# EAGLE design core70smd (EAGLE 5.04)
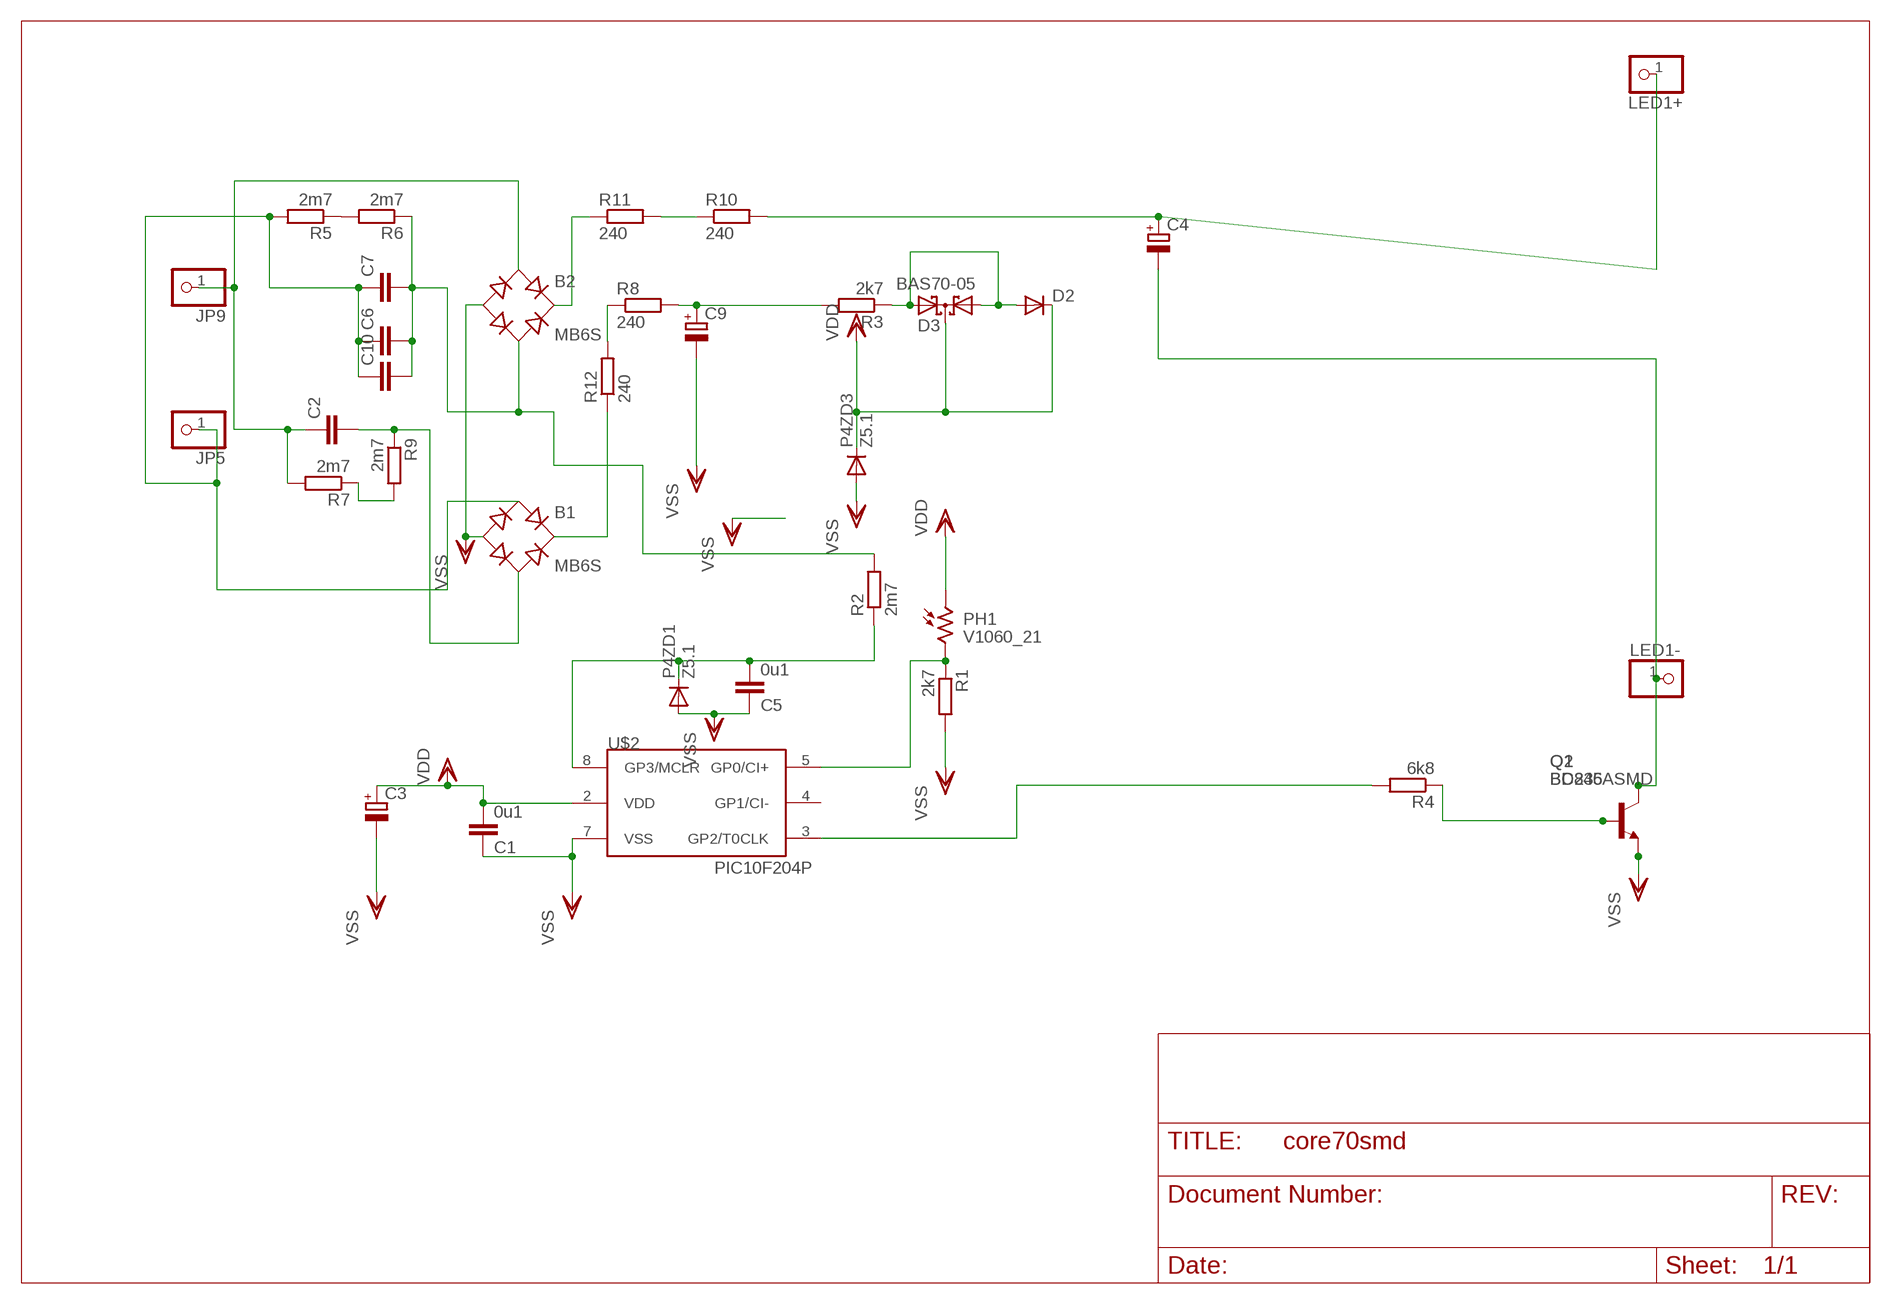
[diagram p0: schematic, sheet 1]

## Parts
B1  MB6S  [SOIC-4]
B2  MB6S  [SOIC-4]
C1  0u1  C-EUC1206  [C1206]
C2  C-EUC4564  [C4564]
C3  CPOL-EUB  [PANASONIC_B]
C4  CPOL-EUSMCE  [SMC_E]
C5  0u1  C-EUC1206  [C1206]
C6  C-EUC4564  [C4564]
C7  C-EUC4564  [C4564]
C9  CPOL-EUSMCD  [SMC_D]
C10  C-EUC4564  [C4564]
D2  DIODE-MINIMELF  [MINIMELF]
D3  BAS70-05  [SOT23]
JP5  PINHD-1X1  [1X01]
JP9  PINHD-1X1  [1X01]
LED1+  PINHD-1X1  [1X01]
LED1-  PINHD-1X1  [1X01]
P4ZD1  Z5.1  DIODE-MINIMELF  [MINIMELF]
P4ZD3  Z5.1  DIODE-MINIMELF  [MINIMELF]
PH1  V1060_21  [TO-5_V10]
Q1  BC846ASMD  [SOT23]
Q2  BD235  [TO126]
R1  2k7  R-EU_R1206  [R1206]
R2  2m7  R-EU_R1206  [R1206]
R3  2k7  R-EU_R1206  [R1206]
R4  6k8  R-EU_R1206  [R1206]
R5  2m7  R-EU_R1210  [R1210]
R6  2m7  R-EU_R1210  [R1210]
R7  2m7  R-EU_R1210  [R1210]
R8  240  R-EU_R1210  [R1210]
R9  2m7  R-EU_R1210  [R1210]
R10  240  R-EU_R2010  [R2010]
R11  240  R-EU_R2010  [R2010]
R12  240  R-EU_R1210  [R1210]
U$2  PIC10F204P  [DIL8]

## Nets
AC1: B1.~1(AC1) C6.1 C7.1 C10.1 JP5.1 R5.2
AC2: B2.~1(AC1) C2.1 JP9.1 R7.2
CBIG: B2.~2(AC2) C6.2 C7.2 C10.2 R2.2 R6.1
CSMALL: B1.~2(AC2) C2.2 R9.1
D+: C4.+ LED1+.1 R10.2
D-: C4.- LED1-.1 Q1.3(C) Q2.2(C)
DR+: C9.+ R3.2 R8.2
N$1: C5.2 P4ZD1.C R2.1 U$2.8(GP3/MCLR)
N$2: R5.1 R6.2
N$3: R7.1 R9.2
N$4: R8.1 R12.2
N$5: D2.A D3.1(A1) D3.2(A2) R3.1
N$6: R10.1 R11.2
N$11: B2.+ R11.1
N$12: Q1.1(B) Q2.3(B) R4.1
N$15: R4.2 U$2.3(GP2/T0CLK)
N$17: PH1.2 R1.1 U$2.5(GP0/CI+)
RECDR+: B1.+ R12.1
VDD: C1.2 C3.+ D2.C D3.3(C) P4ZD3.C PH1.1 U$2.2(VDD)
VSS: B1.- B2.- C1.1 C3.- C5.1 C9.- P4ZD1.A P4ZD3.A Q1.2(E) Q2.1(E) R1.2 U$2.7(VSS)
Unconnected: U$2.4(GP1/CI-)

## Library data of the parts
B1 B2 = rectifier:MB*S: Bridge Rectifier Source: http://www.fairchildsemi.com/ds/MB/MB6S.pdf
C1 C5 = rcl:C-EU: CAPACITOR, European symbol
C2 C6 C7 C10 = rcl-2:C-EU: CAPACITOR, European symbol
C3 C4 C9 = rcl-2:CPOL-EU: POLARIZED CAPACITOR, European symbol
D2 P4ZD1 P4ZD3 = diode:DIODE-: DIODE
D3 = diode:BAS70-05: Silicon Schottky Diodes General-purpose diode for high-speed switching
JP5 JP9 LED1+ LED1- = pinhead(2):PINHD-1X1: PIN HEADER
PH1 = photo-elements:?1060*: Sensor Street Light control
Q1 = transistor-npn:BC846*: NPN Transistor
Q2 = transistor-npn:BD235*: NPN Transistor
R1-R12 = rcl-2:R-EU_: RESISTOR, European symbol
U$2 = microchip-3:PIC10F2*: uPC nW 0,25/0,5k Program Flash memory Comparator

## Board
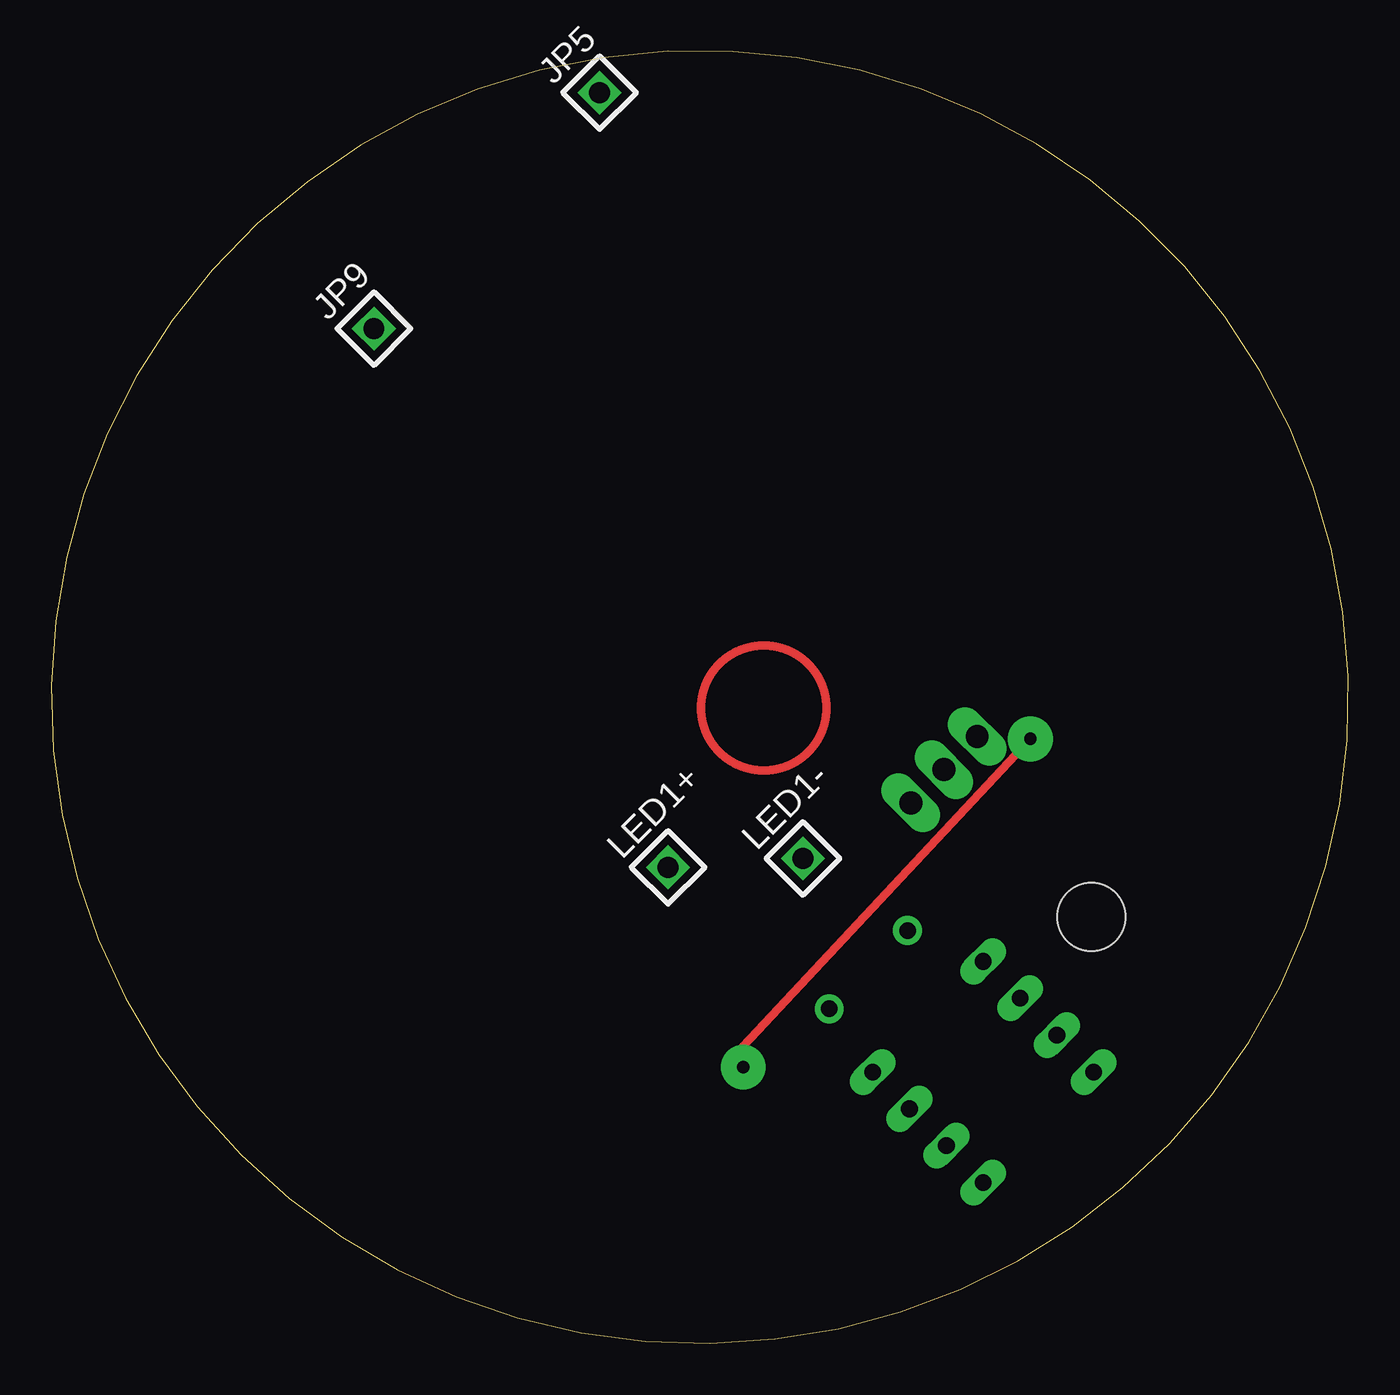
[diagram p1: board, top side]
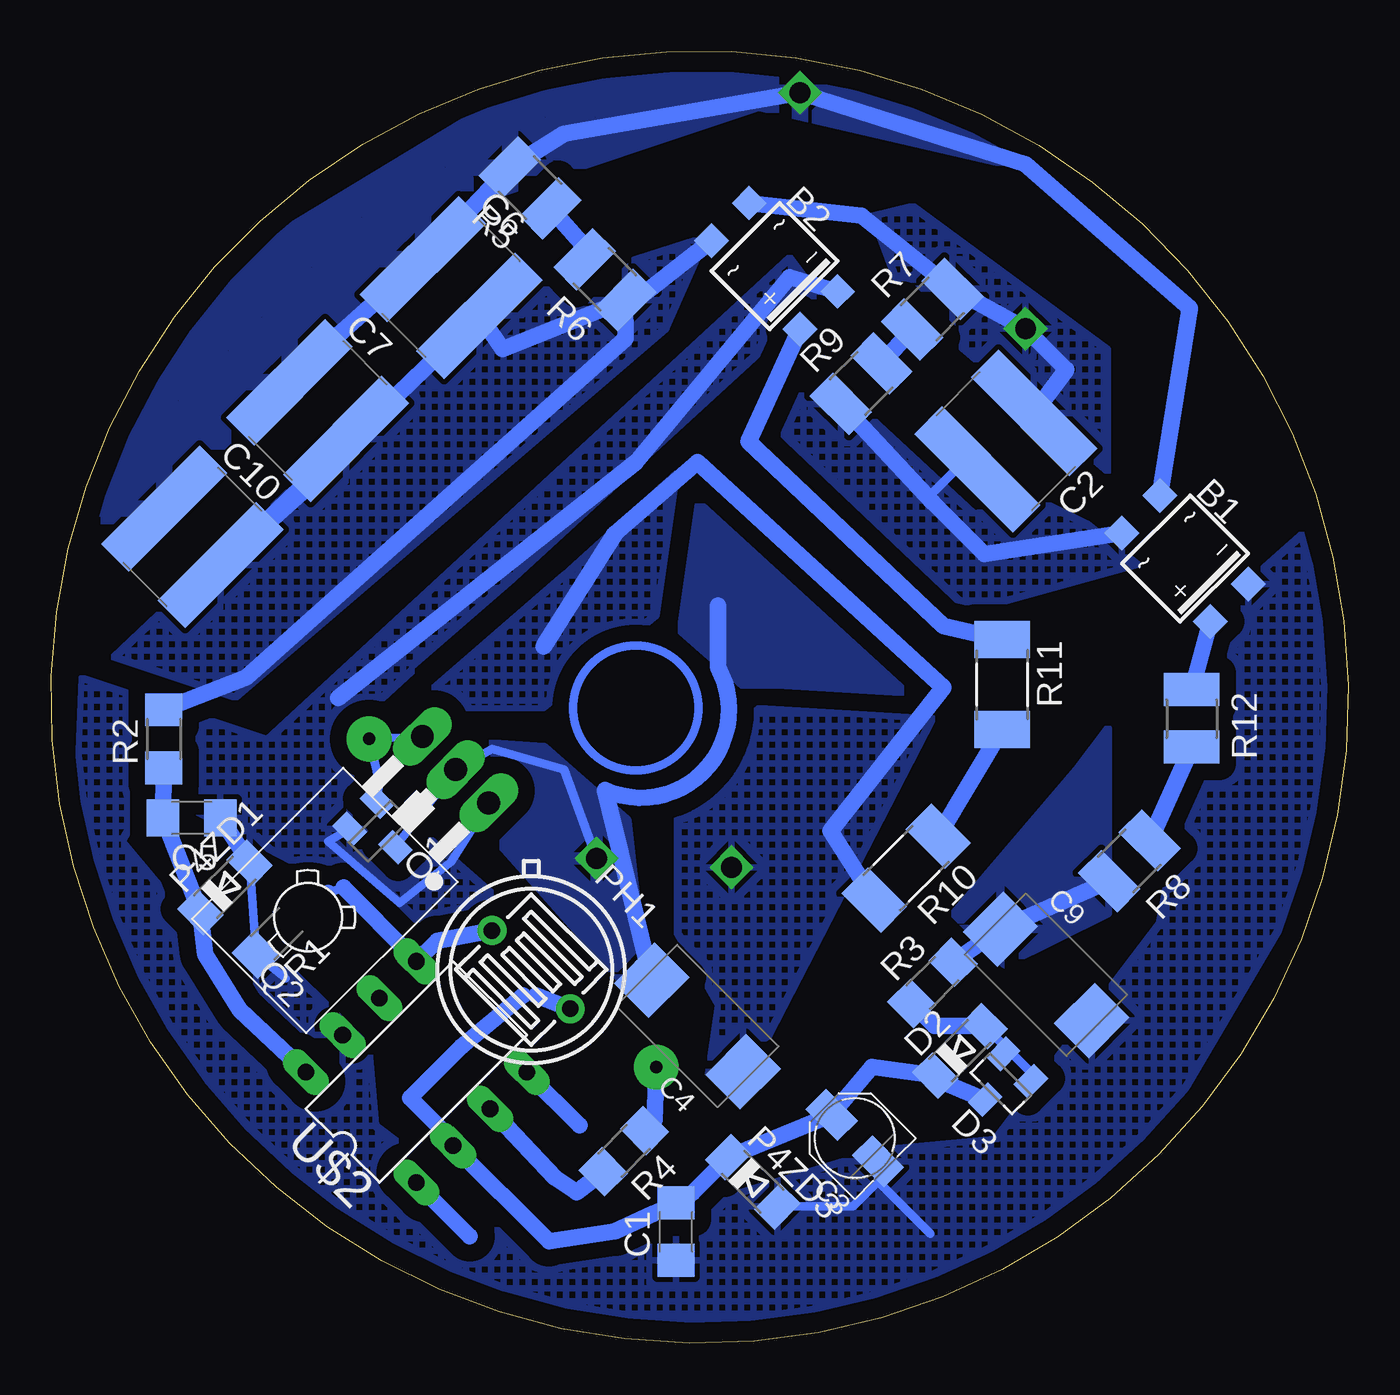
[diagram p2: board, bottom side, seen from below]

Size 63.22 x 62.98 mm. Coordinates in mm from the lower left corner, seen from the top.
Outline: 35.28,0.22 arc171 33.23,62.97 arc190 35.28,0.22
Copper layers (1*16): Top 0.035mm / dielectric 1.5mm / Bottom 0.035mm
Design rules "default": minimum track width 10mil, minimum drill 24mil, track to track 8mil, track to pad 8mil, pad to pad 8mil, via to via 8mil, smd to smd 8mil, copper to edge 40mil, drill to drill 8mil, minimum pad ring 10mil, minimum via ring 8mil, stop-mask expansion 4mil, vias tented up to drill 0mil, thermal gap 10mil

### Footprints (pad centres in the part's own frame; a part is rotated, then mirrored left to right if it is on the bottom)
SOIC-4 = smd 1.2 x 1.2: + 1.3,3.05; - -1.3,3.05; ~1 -1.3,-3.05; ~2 1.3,-3.05
C1206 = smd 1.6 x 1.8: 1 -1.4,0; 2 1.4,0
C4564 = smd 1.9 x 6.8: 1 -1.95,0; 2 1.95,0
PANASONIC_B = smd 2.2 x 1.4: + 1.6,0; - -1.6,0
SMC_E = smd 2.4 x 2.8: + -3.15,0; - 3.15,0
SMC_D = smd 2.4 x 2.8: + -3.15,0; - 3.15,0
MINIMELF = smd 1.4 x 1.8: A 1.7,0; C -1.7,0
SOT23 = smd 1 x 1.4: 1 -0.95,-1.1; 2 0.95,-1.1; 3 0,1.1
1X01 = drill 1.016 square: 1 0,0
TO-5_V10 = drill 0.8 pad 1.4 round: 1 -2.7,0; 2 2.7,0
TO126 = drill 1.118 long: 1 -2.286,-5.08; 2 0,-5.08; 3 2.286,-5.08 | hole 3.302: 0,5.08
R1206 = smd 1.6 x 1.803: 1 -1.422,0; 2 1.422,0
R1210 = smd 1.6 x 2.7: 1 -1.4,0; 2 1.4,0
R2010 = smd 1.8 x 2.7: 1 -2.2,0; 2 2.2,0
DIL8 = drill 0.813 long: 1 -3.81,-3.81; 2 -1.27,-3.81; 3 1.27,-3.81; 4 3.81,-3.81; 5 3.81,3.81; 6 1.27,3.81; 7 -1.27,3.81; 8 -3.81,3.81

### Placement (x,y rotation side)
B1  7.95,38.26 225 bottom
B2  27.96,52.52 225 bottom
C1  32.77,5.45 90 bottom
C2  16.69,43.98 225 bottom
C3  24.05,10.01 135 bottom
C4  31.73,15.47 135 bottom
C5  56.37,25.62 180 bottom
C6  43.73,51.47 315 bottom
C7  50.23,45.47 315 bottom
C9  14.73,17.97 315 bottom
C10  56.34,39.31 315 bottom
D2  18.93,14.27 45 bottom
D3  16.92,12.66 135 bottom
JP5  26.73,60.97 45 top
JP9  15.73,49.47 45 top
LED1+  30.07,23.21 45 top
LED1-  36.64,23.64 45 top
P4ZD1  54.75,22.23 45 bottom
P4ZD3  29.03,7.88 315 bottom
PH1  39.83,18.22 135 bottom
Q1  47.23,24.97 225 bottom
Q2  47.1,24.38 135 bottom
R1  52.23,19.97 225 bottom
R2  57.73,29.47 90 bottom
R3  20.27,17.57 45 bottom
R4  35.3,9.37 225 bottom
R5  39.87,56.32 135 bottom
R6  36.23,51.85 135 bottom
R7  20.27,50.41 45 bottom
R8  10.66,23.53 225 bottom
R9  23.74,46.78 45 bottom
R10  21.54,23.17 225 bottom
R11  16.87,32.12 270 bottom
R12  7.63,30.47 270 bottom
U$2  45.42,13.23 45 bottom

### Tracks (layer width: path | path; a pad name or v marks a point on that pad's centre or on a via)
AC1
  Bottom 0.813: B1.~1 7.73,50.47 15.73,57.47 JP5.1 38.23,58.97 R5.2 C6.1 52.23,46.47 C7.1
  pour Bottom (isolate 0.813, rank 4, hatched): 25.73,62.97 38.73,61.97 55.23,51.97 61.23,39.97 60.23,38.97 42.23,55.97 28.73,60.47 15.73,57.47
AC2
  Bottom 0.813: B2.~1 23.73,54.97 R7.2 JP9.1 13.73,47.47 C2.1
  pour Bottom (isolate 0.813, rank 3, hatched): 23.23,54.97 21.23,55.47 11.73,48.47 11.73,42.47 21.73,50.97
CBIG
  Bottom 0.813: B2.~2 35.23,50.47 R6.1 | R6.1 41.23,48.47 C6.2 C10.2 48.23,43.97 C7.2 | R2.2 53.73,32.47 35.23,48.97 R6.1
  pour Bottom (isolate 0.813, rank 3, hatched): 31.23,53.97 33.23,49.47 54.23,31.47 60.23,33.47 42.23,50.47
CSMALL
  Bottom 0.406: C2.2 19.11,42.6 20.48,41.24
  Bottom 0.813: B1.~2 17.73,38.47 20.23,40.97 R9.1
  pour Bottom (isolate 0.813, rank 3, hatched): 25.23,46.97 27.23,45.97 27.73,43.47 19.23,35.47 10.23,37.97 12.73,39.97 14.73,40.97 18.23,40.47
D+
  Bottom 0.813: R10.2 25.23,24.97 19.73,31.97 31.73,42.97 35.73,39.47 39.23,33.97
  pour Bottom (isolate 0.813, hatched): 38.23,37.47 45.73,30.97 39.23,30.97 33.73,35.47 32.73,42.47
  pour Bottom (isolate 0.813, hatched): 28.23,14.97 20.23,30.47 28.73,30.97 32.73,27.47 32.73,19.97 30.73,16.47 31.23,12.97
D-
  Bottom 0.406: LED1-.1 38.23,27.97 41.73,28.97 Q2.2 Q1.3
  Bottom 0.813: C4.- 36.23,26.97 arc-143 30.73,32.97 30.73,35.97
  pour Bottom (isolate 0.813, rank 2): 42.23,25.47 34.23,16.47 35.23,25.47 39.23,28.97 46.23,29.47
  pour Bottom (isolate 0.813, rank 2): 24.23,34.47 32.73,41.97 33.23,35.47 29.23,31.97 20.73,31.47
DR+
  Bottom 0.813: R8.2 C9.+ R3.2
  pour Bottom: 13.23,27.97 19.23,20.97 16.73,18.47 11.73,20.97 11.73,29.97
N$1
  Bottom 0.813: U$2.8 54.03,16.27 55.73,18.97 P4ZD1.C C5.2 R2.1
N$2
  Bottom 0.813: R5.1 37.23,53.47 R6.2
N$3
  Bottom 0.813: R7.1 R9.2
N$4
  Bottom 0.813: R8.1 R12.2
N$5
  Bottom 0.406: D3.1 15.47,13.21 D2.A 16.82,14.56 D3.2
  Bottom 0.813: D2.A 20.17,15.47 R3.1
N$6
  Bottom 0.813: R10.1 R11.2
N$7
  Bottom 0.813: 37.48,10.62 39.98,13.12
N$8
  Bottom 0.813: 42.83,5.22 45.33,7.72
N$11
  Bottom 0.813: B2.+ 29.23,43.97 19.73,34.97 R11.1
N$12  (via drill 0.6 pad 2.18)
  Top 0.406: v33.73,13.47 33.73,14.47 v47.73,29.47
  Bottom 0.406: R4.1 33.82,10.88 | Q1.1 47.23,27.41 v47.73,29.47 Q2.3
  Bottom 0.813: 33.82,10.88 v33.73,13.47
N$15
  Bottom 0.406: 37.62,7.37 37.73,7.47
  Bottom 0.813: R4.2 37.62,7.37 | 37.73,7.47 38.67,8.07 U$2.3
N$17
  Bottom 0.406: U$2.5 45.63,18.87 | 48.98,22.22 49.73,21.97
  Bottom 0.813: PH1.2 44.42,19.63 U$2.5 | 45.63,18.87 48.98,22.22 | 49.73,21.97 R1.1
RECDR+
  Bottom 0.813: R12.1 B1.+
VDD
  Bottom 0.406: U$2.2 43.63,9.87 | 40.23,16.97 39.58,16.97
  Bottom 0.813: 20.7,13.14 D2.C | 20.7,13.14 23.23,13.47 C3.+ P4ZD3.C 31.96,7.35 C1.2 33.85,6.35 35.73,5.47 38.96,4.97 U$2.2 | D3.3 20.7,13.14 | 43.63,9.87 45.73,11.97 43.23,14.47 40.23,16.97 | 39.58,16.97 PH1.1
VSS
  Bottom 0.406: 51.79,17.8 R1.2 P4ZD1.A | 22.92,7.91 C3.- | 20.36,5.35 22.92,7.91 | P4ZD3.A 24.15,6.68 22.92,7.91 | Q2.1 43.73,23.47 46.23,21.47 49.73,24.47 Q1.2
  Bottom 0.813: B2.- 27.23,51.97 34.73,42.97 49.23,31.47 | P4ZD1.A C5.1
  pour Bottom (isolate 0.813, rank 4, hatched): 1.73,39.97 6.23,35.97 9.23,20.47 17.23,9.97 22.73,9.47 39.23,4.47 47.38,10.62 47.73,14.47 53.23,19.97 54.73,18.47 59.73,24.47 58.23,26.97 44.73,19.97 41.73,21.97 49.73,28.97 25.73,50.97 27.23,52.97 52.73,29.47 61.73,32.47 62.23,20.47 arc-37 45.63,2.67 arc-8 28.63,-0.33 arc-42 10.23,8.47 0.23,25.47
(copper drawn outside any net)
  shapes: Bottom circle x1, Top circle x1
